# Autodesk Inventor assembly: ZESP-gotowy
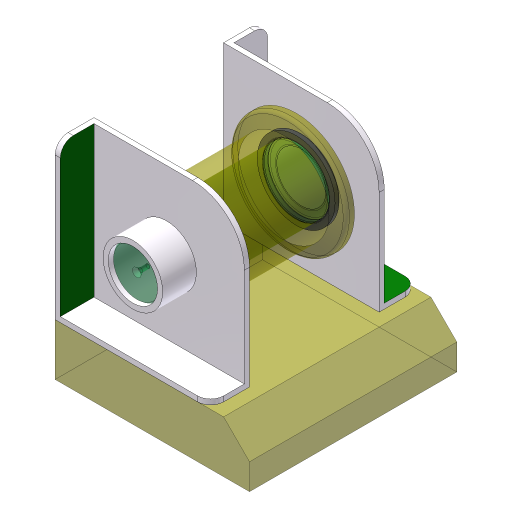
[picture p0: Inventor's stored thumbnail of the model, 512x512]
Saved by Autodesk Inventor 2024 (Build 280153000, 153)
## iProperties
Company: ATC
Created: 2023-03
Part Number: ZESP-gotowy
Document SubType Name: Assembly
Designer: Andrzej Jaskulski
Mass: 1986.93 g
Surface Area: 612.19 cm^2
Volume: 198.693 cm^3
Density: 10 g/cm^3
Stock Number: ZESP-gotowy
Checked By: A.J.
Engr Approved By: Andrzej Jaskulski
Mfg Approved By: Andrzej Jaskulski
Authority: A.J.
Title: A.J.: Kurs R2024-MEP
Author: Andrzej Jaskulski
Revision Number: 1/24
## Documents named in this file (4)
- C:\Users\AndJas\Documents\R2024-MEP\Obszar roboczy\ZESP-gotowy.iam
- C:\Users\AndJas\Documents\R2024-MEP\Obszar roboczy\PŁYTA.ipt
- C:\Users\AndJas\Documents\R2024-MEP\Obszar roboczy\WSP.ipt
- C:\Users\AndJas\Documents\R2024-MEP\Obszar roboczy\PZESP1.iam
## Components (4 placed, 3 different names)
1. PŁYTA:1 — Zestawiający:1, Zestawiający:2, Zestawiający:3, Zestawiający:4
2. WSP:1 — Zestawiający:1, Zestawiający:3, Wstaw:1
3. WSP:2 — Zestawiający:2, Zestawiający:4
4. PZESP1:1 [sub-assembly] — Wstaw:1
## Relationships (5: Mate 4, Insert 1)
- Zestawiający:1 [Mate]: PŁYTA:1 ↔ WSP:1
- Zestawiający:2 [Mate]: PŁYTA:1 ↔ WSP:2
- Zestawiający:3 [Mate]: PŁYTA:1 ↔ WSP:1
- Zestawiający:4 [Mate]: PŁYTA:1 ↔ WSP:2
- Wstaw:1 [Insert]: WSP:1 ↔ PZESP1:1
